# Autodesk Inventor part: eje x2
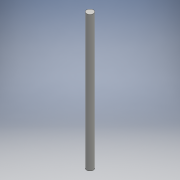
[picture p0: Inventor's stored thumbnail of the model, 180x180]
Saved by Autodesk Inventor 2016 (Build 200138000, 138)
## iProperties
Created: 2016-06
Part Number: eje x2
Material: Genérico
Document SubType Name: Modeling
Designer: adm
Density: 1 g/cm^3
Appearance: Valor por defecto
Author: adm
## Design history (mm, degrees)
sketch "Boceto1"
  geometry: C1 r 5 at (0, 0); 1 further point
  constraints: 1 centre point, 1 coincident
  dimensions: "d0" = 10 diameter of C1
extrude "Extrusión1" new body sketch "Boceto1" distance "d1" = 200; taper "d2" = 0 deg
node "Sólido1"
